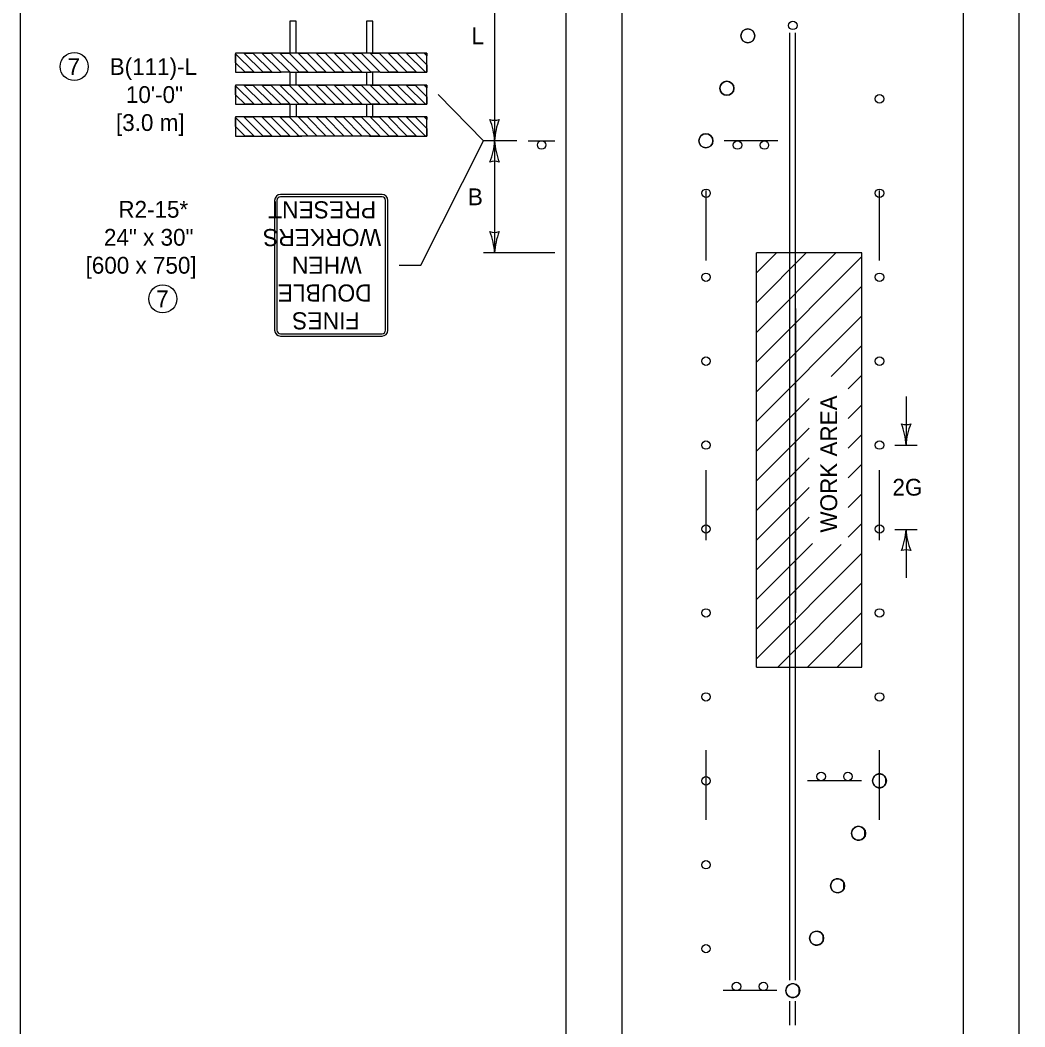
# Model space of a CAD drawing. Extents: x 49991.4 to 50021, y 49987.6 to 50011.4.
# Drawn here: x 50000.336 to 50003.928, y 50003.697 to 50007.296 of the extents above; entities that cross this region are included whole.
import ezdxf

# ---------------------------------------------------------------- set-up
doc = ezdxf.new("R2010")
doc.units = 0
for name, color, linetype in [('Level 1', 7, 'Continuous'), ('Level 2', 7, 'Continuous'), ('Level 3', 7, 'Continuous')]:
    doc.layers.add(name, color=color, linetype=linetype)

msp = doc.modelspace()

# ---------------------------------------------------------------- linework, layer by layer
at = {"layer": 'Level 1'}
for p, q in [((50002.2878, 50001.0309), (50002.2878, 50009.6868)), ((50002.4877, 50001.0309), (50002.4877, 50009.6868)), ((50003.7077, 50001.0309), (50003.7077, 50009.6868)), ((50003.9076, 50001.0309), (50003.9076, 50009.6868)), ((50003.0877, 50003.9389), (50003.0877, 50007.2508)), ((50003.1077, 50004.0147), (50003.1077, 50007.2503)), ((50001.106, 50007.1751), (50001.1719, 50007.1092)), ((50001.106, 50007.1751), (50001.1719, 50007.1092)), ((50001.1357, 50007.1776), (50001.2041, 50007.1092)), ((50001.2041, 50007.1092), (50001.1357, 50007.1776)), ((50001.1679, 50007.1776), (50001.2363, 50007.1092)), ((50001.1679, 50007.1776), (50001.2363, 50007.1092)), ((50001.2002, 50007.1776), (50001.2686, 50007.1092)), ((50001.2686, 50007.1092), (50001.2002, 50007.1776)), ((50001.2324, 50007.1776), (50001.3008, 50007.1092)), ((50001.2324, 50007.1776), (50001.3008, 50007.1092)), ((50001.2646, 50007.1776), (50001.333, 50007.1092)), ((50001.333, 50007.1092), (50001.2646, 50007.1776)), ((50001.2969, 50007.1776), (50001.3653, 50007.1092)), ((50001.2969, 50007.1776), (50001.3653, 50007.1092)), ((50001.3291, 50007.1776), (50001.3975, 50007.1092)), ((50001.3975, 50007.1092), (50001.3291, 50007.1776)), ((50001.3614, 50007.1776), (50001.4297, 50007.1092)), ((50001.3614, 50007.1776), (50001.4297, 50007.1092)), ((50001.3936, 50007.1776), (50001.4619, 50007.1092)), ((50001.4619, 50007.1092), (50001.3936, 50007.1776)), ((50001.4258, 50007.1776), (50001.4942, 50007.1092)), ((50001.4258, 50007.1776), (50001.4942, 50007.1092)), ((50001.4581, 50007.1776), (50001.5265, 50007.1092)), ((50001.5265, 50007.1092), (50001.4581, 50007.1776)), ((50001.4903, 50007.1776), (50001.5587, 50007.1092)), ((50001.4903, 50007.1776), (50001.5587, 50007.1092)), ((50001.5225, 50007.1776), (50001.5909, 50007.1092)), ((50001.5909, 50007.1092), (50001.5225, 50007.1776)), ((50001.5547, 50007.1776), (50001.6231, 50007.1092)), ((50001.5547, 50007.1776), (50001.6231, 50007.1092)), ((50001.587, 50007.1776), (50001.6554, 50007.1092)), ((50001.6554, 50007.1092), (50001.587, 50007.1776)), ((50001.6192, 50007.1776), (50001.6876, 50007.1092)), ((50001.6192, 50007.1776), (50001.6876, 50007.1092)), ((50001.6514, 50007.1776), (50001.7198, 50007.1092)), ((50001.7198, 50007.1092), (50001.6514, 50007.1776)), ((50001.6837, 50007.1776), (50001.7521, 50007.1092)), ((50001.6837, 50007.1776), (50001.7521, 50007.1092)), ((50001.716, 50007.1776), (50001.7844, 50007.1092)), ((50001.7844, 50007.1092), (50001.716, 50007.1776)), ((50001.7482, 50007.1776), (50001.7899, 50007.1359)), ((50001.7482, 50007.1776), (50001.7899, 50007.1359)), ((50001.7804, 50007.1776), (50001.7899, 50007.1681)), ((50001.7899, 50007.1681), (50001.7804, 50007.1776)), ((50001.106, 50007.1429), (50001.1396, 50007.1092)), ((50001.1396, 50007.1092), (50001.106, 50007.1429)), ((50001.106, 50007.0611), (50001.1719, 50006.9953)), ((50001.106, 50007.0611), (50001.1719, 50006.9953)), ((50001.106, 50007.0289), (50001.1396, 50006.9953)), ((50001.1396, 50006.9953), (50001.106, 50007.0289)), ((50001.1357, 50007.0637), (50001.2041, 50006.9953)), ((50001.2041, 50006.9953), (50001.1357, 50007.0637)), ((50001.1679, 50007.0637), (50001.2363, 50006.9953)), ((50001.1679, 50007.0637), (50001.2363, 50006.9953)), ((50001.2002, 50007.0637), (50001.2686, 50006.9953)), ((50001.2686, 50006.9953), (50001.2002, 50007.0637)), ((50001.2324, 50007.0637), (50001.3008, 50006.9953)), ((50001.2324, 50007.0637), (50001.3008, 50006.9953)), ((50001.2646, 50007.0637), (50001.333, 50006.9953)), ((50001.2969, 50007.0637), (50001.3653, 50006.9953)), ((50001.3291, 50007.0637), (50001.3975, 50006.9953)), ((50001.3614, 50007.0637), (50001.4297, 50006.9953)), ((50001.3936, 50007.0637), (50001.4619, 50006.9953)), ((50001.4258, 50007.0637), (50001.4942, 50006.9953)), ((50001.4581, 50007.0637), (50001.5265, 50006.9953)), ((50001.4903, 50007.0637), (50001.5587, 50006.9953)), ((50001.5225, 50007.0637), (50001.5848, 50007.0015)), ((50001.5547, 50007.0637), (50001.5848, 50007.0337)), ((50001.5848, 50007.0337), (50001.6231, 50006.9953)), ((50001.587, 50007.0637), (50001.6554, 50006.9953)), ((50001.6554, 50006.9953), (50001.587, 50007.0637)), ((50001.6192, 50007.0637), (50001.6876, 50006.9953)), ((50001.6192, 50007.0637), (50001.6876, 50006.9953)), ((50001.6514, 50007.0637), (50001.7198, 50006.9953)), ((50001.7198, 50006.9953), (50001.6514, 50007.0637)), ((50001.6837, 50007.0637), (50001.7521, 50006.9953)), ((50001.6837, 50007.0637), (50001.7521, 50006.9953)), ((50001.716, 50007.0637), (50001.7844, 50006.9953)), ((50001.7844, 50006.9953), (50001.716, 50007.0637)), ((50001.7482, 50007.0637), (50001.7899, 50007.022)), ((50001.7482, 50007.0637), (50001.7899, 50007.022)), ((50001.7804, 50007.0637), (50001.7899, 50007.0542)), ((50001.7899, 50007.0542), (50001.7804, 50007.0637)), ((50001.3226, 50006.9953), (50001.3226, 50006.9498)), ((50001.5734, 50006.9953), (50001.5734, 50006.9498)), ((50001.5848, 50007.0015), (50001.5909, 50006.9953)), ((50001.106, 50006.9472), (50001.1719, 50006.8814)), ((50001.106, 50006.9472), (50001.1719, 50006.8814)), ((50001.1357, 50006.9498), (50001.2041, 50006.8814)), ((50001.2041, 50006.8814), (50001.1357, 50006.9498)), ((50001.1679, 50006.9498), (50001.2363, 50006.8814)), ((50001.1679, 50006.9498), (50001.2363, 50006.8814)), ((50001.2002, 50006.9498), (50001.2686, 50006.8814)), ((50001.2686, 50006.8814), (50001.2002, 50006.9498)), ((50001.2324, 50006.9498), (50001.3008, 50006.8814)), ((50001.2324, 50006.9498), (50001.3008, 50006.8814)), ((50001.2646, 50006.9498), (50001.333, 50006.8814)), ((50001.2969, 50006.9498), (50001.3653, 50006.8814)), ((50001.3293, 50006.9498), (50001.3977, 50006.8814)), ((50001.3615, 50006.9498), (50001.4299, 50006.8814)), ((50001.3937, 50006.9498), (50001.4621, 50006.8814)), ((50001.4259, 50006.9498), (50001.4943, 50006.8814)), ((50001.4581, 50006.9498), (50001.5265, 50006.8814)), ((50001.4903, 50006.9498), (50001.5587, 50006.8814)), ((50001.5225, 50006.9498), (50001.5909, 50006.8814)), ((50001.5547, 50006.9498), (50001.6231, 50006.8814)), ((50001.587, 50006.9498), (50001.6554, 50006.8814)), ((50001.6554, 50006.8814), (50001.587, 50006.9498)), ((50001.6192, 50006.9498), (50001.6876, 50006.8814)), ((50001.6192, 50006.9498), (50001.6876, 50006.8814)), ((50001.6514, 50006.9498), (50001.7198, 50006.8814)), ((50001.7198, 50006.8814), (50001.6514, 50006.9498)), ((50001.6837, 50006.9498), (50001.7521, 50006.8814)), ((50001.6837, 50006.9498), (50001.7521, 50006.8814)), ((50001.716, 50006.9498), (50001.7844, 50006.8814)), ((50001.7844, 50006.8814), (50001.716, 50006.9498)), ((50001.7482, 50006.9498), (50001.7899, 50006.908)), ((50001.7482, 50006.9498), (50001.7899, 50006.908)), ((50001.7804, 50006.9498), (50001.7899, 50006.9403)), ((50001.7899, 50006.9403), (50001.7804, 50006.9498)), ((50001.106, 50006.915), (50001.1396, 50006.8814)), ((50001.1396, 50006.8814), (50001.106, 50006.915)), ((50001.3112, 50006.8814), (50001.3425, 50006.8814)), ((50001.5705, 50006.8814), (50001.3254, 50006.8814)), ((50001.5909, 50006.8814), (50001.551, 50006.8814)), ((50002.1518, 50006.8644), (50002.2478, 50006.8644)), ((50002.9483, 50006.8644), (50002.8523, 50006.8644)), ((50003.0443, 50006.8644), (50002.9483, 50006.8644)), ((50001.6294, 50006.6726), (50001.2665, 50006.6726)), ((50002.7879, 50006.4368), (50002.7879, 50006.6868)), ((50003.4079, 50006.4368), (50003.4079, 50006.6868)), ((50001.2454, 50006.6515), (50001.2454, 50006.1874)), ((50001.2539, 50006.6515), (50001.2539, 50006.1874)), ((50001.6294, 50006.6642), (50001.2665, 50006.6642)), ((50001.6421, 50006.1874), (50001.6421, 50006.6515)), ((50001.6505, 50006.1874), (50001.6505, 50006.6515)), ((50003.3453, 50006.4637), (50002.9682, 50006.4637)), ((50002.9682, 50004.9833), (50002.9682, 50006.4637)), ((50002.9682, 50006.2856), (50003.1463, 50006.4637)), ((50002.9682, 50006.1795), (50003.2524, 50006.4637)), ((50002.9682, 50006.3918), (50003.0401, 50006.4637)), ((50003.3453, 50004.9833), (50003.3453, 50006.4637)), ((50002.9682, 50006.0735), (50003.3453, 50006.4506)), ((50002.9682, 50005.9674), (50003.3453, 50006.3445)), ((50002.9682, 50005.8613), (50003.3453, 50006.2384)), ((50003.1077, 50006.2644), (50003.1077, 50005.1767)), ((50001.2665, 50006.1747), (50001.6294, 50006.1747)), ((50001.2665, 50006.1663), (50001.6294, 50006.1663)), ((50003.2349, 50006.0219), (50003.3453, 50006.1324)), ((50003.2965, 50005.9775), (50003.3453, 50006.0263)), ((50002.9682, 50005.7553), (50003.1565, 50005.9436)), ((50003.2965, 50005.8714), (50003.3453, 50005.9202)), ((50003.2965, 50005.8714), (50003.2965, 50005.8714)), ((50002.9682, 50005.6492), (50003.1565, 50005.8375)), ((50003.2965, 50005.7654), (50003.3453, 50005.8142)), ((50003.2965, 50005.7654), (50003.2965, 50005.7654)), ((50002.9682, 50005.5432), (50003.1565, 50005.7314)), ((50003.2965, 50005.6593), (50003.3453, 50005.7081)), ((50002.7879, 50005.4368), (50002.7879, 50005.6868)), ((50003.4079, 50005.4368), (50003.4079, 50005.6868)), ((50002.9682, 50005.4371), (50003.1565, 50005.6254)), ((50003.2965, 50005.6593), (50003.2965, 50005.6593)), ((50003.2965, 50005.5532), (50003.3453, 50005.602)), ((50002.9682, 50005.331), (50003.1565, 50005.5193)), ((50003.2965, 50005.4472), (50003.3453, 50005.496)), ((50002.9682, 50005.1189), (50003.2705, 50005.4211)), ((50002.9682, 50005.225), (50003.1565, 50005.4132)), ((50003.1565, 50005.4132), (50003.1684, 50005.4251)), ((50002.9682, 50005.0128), (50003.3453, 50005.3899)), ((50003.0448, 50004.9833), (50003.3453, 50005.2838)), ((50003.1509, 50004.9833), (50003.3453, 50005.1778)), ((50003.2569, 50004.9833), (50003.3453, 50005.0717)), ((50002.9682, 50004.9833), (50003.3453, 50004.9833)), ((50002.7879, 50004.4368), (50002.7879, 50004.6868)), ((50003.4079, 50004.4368), (50003.4079, 50004.6868)), ((50003.2471, 50004.5767), (50003.1511, 50004.5767)), ((50003.3431, 50004.5767), (50003.2471, 50004.5767)), ((50003.1077, 50003.8647), (50003.1077, 50004.0147)), ((50003.0877, 50003.8647), (50003.0877, 50003.9389)), ((50002.9448, 50003.8267), (50002.8488, 50003.8267)), ((50003.0408, 50003.8267), (50002.9448, 50003.8267)), ((50003.0877, 50003.7029), (50003.0877, 50003.7887)), ((50003.1077, 50003.7029), (50003.1077, 50003.7887))]:
    msp.add_line(p, q, dxfattribs=at)
msp.add_lwpolyline([(50008.6146, 50011.2628), (50000.3356, 50011.2628), (50000.3356, 50000.0624), (50008.6146, 50000.0624)], close=True, dxfattribs=at)
for points in [[(50001.3226, 50007.1778), (50001.3226, 50007.2917), (50001.2998, 50007.2917), (50001.2998, 50007.1778)], [(50001.5962, 50007.1778), (50001.5962, 50007.2917), (50001.5734, 50007.2917), (50001.5734, 50007.1778)], [(50001.6231, 50007.1092), (50001.7899, 50007.1092), (50001.7899, 50007.1776), (50001.106, 50007.1776), (50001.106, 50007.1092), (50001.2686, 50007.1092)], [(50001.106, 50007.1429), (50001.106, 50007.1751)], [(50001.1357, 50007.1776), (50001.1679, 50007.1776)], [(50001.2002, 50007.1776), (50001.2324, 50007.1776)], [(50001.2646, 50007.1776), (50001.2969, 50007.1776)], [(50001.3291, 50007.1776), (50001.3614, 50007.1776)], [(50001.3936, 50007.1776), (50001.4258, 50007.1776)], [(50001.4581, 50007.1776), (50001.4903, 50007.1776)], [(50001.5225, 50007.1776), (50001.5547, 50007.1776)], [(50001.587, 50007.1776), (50001.6192, 50007.1776)], [(50001.6514, 50007.1776), (50001.6837, 50007.1776)], [(50001.716, 50007.1776), (50001.7482, 50007.1776)], [(50001.7804, 50007.1776), (50001.7899, 50007.1776), (50001.7899, 50007.1681)], [(50001.1719, 50007.1092), (50001.1396, 50007.1092)], [(50001.2363, 50007.1092), (50001.2041, 50007.1092)], [(50001.3008, 50007.1092), (50001.2686, 50007.1092)], [(50001.2998, 50007.1092), (50001.2998, 50007.0637)], [(50001.3008, 50007.1092), (50001.5909, 50007.1092)], [(50001.3226, 50007.0637), (50001.3226, 50007.1092)], [(50001.3653, 50007.1092), (50001.333, 50007.1092)], [(50001.4297, 50007.1092), (50001.3975, 50007.1092)], [(50001.4942, 50007.1092), (50001.4619, 50007.1092)], [(50001.5587, 50007.1092), (50001.5265, 50007.1092)], [(50001.5734, 50007.1092), (50001.5734, 50007.0637)], [(50001.6231, 50007.1092), (50001.5909, 50007.1092)], [(50001.5962, 50007.0637), (50001.5962, 50007.1092)], [(50001.6876, 50007.1092), (50001.6554, 50007.1092)], [(50001.7521, 50007.1092), (50001.7198, 50007.1092)], [(50001.7899, 50007.1359), (50001.7899, 50007.1092), (50001.7844, 50007.1092)], [(50001.5848, 50006.9953), (50001.7899, 50006.9953), (50001.7899, 50007.0637), (50001.106, 50007.0637), (50001.106, 50006.9953), (50001.5848, 50006.9953)], [(50001.106, 50007.0289), (50001.106, 50007.0611)], [(50001.1357, 50007.0637), (50001.1679, 50007.0637)], [(50001.2002, 50007.0637), (50001.2324, 50007.0637)], [(50001.3653, 50006.9953), (50001.333, 50006.9953), (50001.2646, 50007.0637), (50001.2969, 50007.0637), (50001.3653, 50006.9953)], [(50001.4297, 50006.9953), (50001.3975, 50006.9953), (50001.3291, 50007.0637), (50001.3614, 50007.0637), (50001.4297, 50006.9953)], [(50001.4942, 50006.9953), (50001.4619, 50006.9953), (50001.3936, 50007.0637), (50001.4258, 50007.0637), (50001.4942, 50006.9953)], [(50001.5587, 50006.9953), (50001.5265, 50006.9953), (50001.4581, 50007.0637), (50001.4903, 50007.0637), (50001.5587, 50006.9953)], [(50001.5225, 50007.0637), (50001.5547, 50007.0637), (50001.5848, 50007.0337), (50001.6231, 50006.9953), (50001.5962, 50006.9953), (50001.5909, 50006.9953), (50001.5848, 50007.0015), (50001.5225, 50007.0637)], [(50001.587, 50007.0637), (50001.6192, 50007.0637)], [(50001.6514, 50007.0637), (50001.6837, 50007.0637)], [(50001.716, 50007.0637), (50001.7482, 50007.0637)], [(50001.7804, 50007.0637), (50001.7899, 50007.0637), (50001.7899, 50007.0542)], [(50001.1719, 50006.9953), (50001.1396, 50006.9953)], [(50001.2363, 50006.9953), (50001.2041, 50006.9953)], [(50001.3008, 50006.9953), (50001.2686, 50006.9953)], [(50001.2998, 50006.9954), (50001.2998, 50006.9498)], [(50001.5962, 50006.9498), (50001.5962, 50006.9953)], [(50001.6876, 50006.9953), (50001.6554, 50006.9953)], [(50001.7521, 50006.9953), (50001.7198, 50006.9953)], [(50001.7899, 50007.022), (50001.7899, 50006.9953), (50001.7844, 50006.9953)], [(50001.5848, 50006.9498), (50001.106, 50006.9498), (50001.106, 50006.8814), (50001.3112, 50006.8814)], [(50001.106, 50006.915), (50001.106, 50006.9472)], [(50001.1357, 50006.9498), (50001.1679, 50006.9498)], [(50001.2002, 50006.9498), (50001.2324, 50006.9498)], [(50001.3653, 50006.8814), (50001.3425, 50006.8814), (50001.333, 50006.8814), (50001.2646, 50006.9498), (50001.2969, 50006.9498), (50001.3653, 50006.8814)], [(50001.4299, 50006.8814), (50001.3977, 50006.8814), (50001.3293, 50006.9498), (50001.3615, 50006.9498), (50001.4299, 50006.8814)], [(50001.4943, 50006.8814), (50001.4621, 50006.8814), (50001.3937, 50006.9498), (50001.4259, 50006.9498), (50001.4943, 50006.8814)], [(50001.5587, 50006.8814), (50001.551, 50006.8814), (50001.5265, 50006.8814), (50001.4581, 50006.9498), (50001.4903, 50006.9498), (50001.5587, 50006.8814)], [(50001.5225, 50006.9498), (50001.5547, 50006.9498), (50001.6231, 50006.8814), (50001.5909, 50006.8814), (50001.5225, 50006.9498)], [(50001.5848, 50006.8814), (50001.7899, 50006.8814), (50001.7899, 50006.9498), (50001.5848, 50006.9498)], [(50001.587, 50006.9498), (50001.6192, 50006.9498)], [(50001.6514, 50006.9498), (50001.6837, 50006.9498)], [(50001.716, 50006.9498), (50001.7482, 50006.9498)], [(50001.7804, 50006.9498), (50001.7899, 50006.9498), (50001.7899, 50006.9403)], [(50001.7899, 50006.908), (50001.7899, 50006.8814), (50001.7844, 50006.8814)], [(50001.1719, 50006.8814), (50001.1396, 50006.8814)], [(50001.2363, 50006.8814), (50001.2041, 50006.8814)], [(50001.3008, 50006.8814), (50001.2686, 50006.8814)], [(50001.6876, 50006.8814), (50001.6554, 50006.8814)], [(50001.7521, 50006.8814), (50001.7198, 50006.8814)], [(50003.4311, 50004.5668), (50003.4311, 50004.5866)], [(50003.4311, 50004.5866), (50003.4311, 50004.5668)], [(50003.356, 50004.3793), (50003.356, 50004.3991)], [(50003.356, 50004.3991), (50003.356, 50004.3793)], [(50003.281, 50004.1918), (50003.281, 50004.2116)], [(50003.281, 50004.2116), (50003.281, 50004.1918)], [(50003.206, 50004.0043), (50003.206, 50004.0241)], [(50003.206, 50004.0241), (50003.206, 50004.0043)], [(50003.1209, 50003.8168), (50003.1209, 50003.8366)], [(50003.1209, 50003.8366), (50003.1209, 50003.8168)]]:
    msp.add_lwpolyline(points, dxfattribs=at)
for centre, radius in [((50003.098, 50007.2767), 0.015), ((50002.9374, 50007.2394), 0.025), ((50002.8624, 50007.0519), 0.025), ((50003.4079, 50007.0144), 0.015), ((50002.7873, 50006.8644), 0.025), ((50002.1999, 50006.8493), 0.0152), ((50002.9003, 50006.8492), 0.0152), ((50002.9963, 50006.8492), 0.0152), ((50002.7879, 50006.6767), 0.015), ((50003.4079, 50006.6767), 0.015), ((50002.7876, 50006.3767), 0.015), ((50003.4079, 50006.3767), 0.015), ((50002.7876, 50006.0767), 0.015), ((50003.4079, 50006.0767), 0.015), ((50002.7876, 50005.7767), 0.015), ((50003.4079, 50005.7767), 0.015), ((50002.7876, 50005.4767), 0.015), ((50003.4079, 50005.4767), 0.015), ((50002.7876, 50005.1767), 0.015), ((50003.4079, 50005.1767), 0.015), ((50002.7876, 50004.8767), 0.015), ((50003.4079, 50004.8767), 0.015), ((50002.7876, 50004.5767), 0.015), ((50003.1991, 50004.5919), 0.0152), ((50003.2951, 50004.5919), 0.0152), ((50003.4081, 50004.5767), 0.025), ((50003.3331, 50004.3892), 0.025), ((50002.7876, 50004.2767), 0.015), ((50003.2581, 50004.2017), 0.025), ((50003.183, 50004.0142), 0.025), ((50002.7876, 50003.9767), 0.015), ((50002.8968, 50003.8419), 0.0152), ((50002.9928, 50003.8419), 0.0152), ((50003.098, 50003.8267), 0.025)]:
    msp.add_circle(centre, radius, dxfattribs=at)
for centre, radius, start, end in [((50002.9374, 50007.2394), 0.025, 0, 180), ((50002.9374, 50007.2394), 0.025, 180, 0), ((50002.8624, 50007.0519), 0.025, 0, 180), ((50002.8624, 50007.0519), 0.025, 180, 0), ((50002.7873, 50006.8644), 0.025, 0, 180), ((50002.7873, 50006.8644), 0.025, 180, 0), ((50001.2665, 50006.6515), 0.0211, 90, 180), ((50001.6293, 50006.6515), 0.0211, 360, 90), ((50001.2665, 50006.6515), 0.0127, 90, 180), ((50001.6293, 50006.6515), 0.0127, 360, 90), ((50001.2665, 50006.1874), 0.0211, 180, 270), ((50001.2665, 50006.1874), 0.0127, 180, 270), ((50001.6293, 50006.1874), 0.0211, 270, 360), ((50001.6293, 50006.1874), 0.0127, 270, 360), ((50003.4081, 50004.5767), 0.025, 23.4057, 180), ((50003.4081, 50004.5767), 0.025, 360, 23.4057), ((50003.4081, 50004.5767), 0.025, 180, 336.5943), ((50003.4081, 50004.5767), 0.025, 336.5943, 0), ((50003.3331, 50004.3892), 0.025, 23.4057, 180), ((50003.3331, 50004.3892), 0.025, 180, 336.5943), ((50003.3331, 50004.3892), 0.025, 360, 23.4057), ((50003.3331, 50004.3892), 0.025, 336.5943, 0), ((50003.2581, 50004.2017), 0.025, 23.4057, 180), ((50003.2581, 50004.2017), 0.025, 180, 336.5943), ((50003.2581, 50004.2017), 0.025, 360, 23.4057), ((50003.2581, 50004.2017), 0.025, 336.5943, 0), ((50003.183, 50004.0142), 0.025, 23.4057, 180), ((50003.183, 50004.0142), 0.025, 180, 336.5943), ((50003.183, 50004.0142), 0.025, 360, 23.4057), ((50003.183, 50004.0142), 0.025, 336.5943, 0), ((50003.098, 50003.8267), 0.025, 23.4057, 180), ((50003.098, 50003.8267), 0.025, 180, 336.5943), ((50003.098, 50003.8267), 0.025, 360, 23.4057), ((50003.098, 50003.8267), 0.025, 336.5943, 0)]:
    msp.add_arc(centre, radius, start, end, dxfattribs=at)
at = {"layer": 'Level 2'}
for centre in [(50000.5289, 50007.1296), (50000.8457, 50006.2994)]:
    msp.add_circle(centre, 0.0501, dxfattribs=at)
at = {"layer": 'Level 3'}
for p, q in [((50002.0318, 50007.6144), (50002.0318, 50006.8644)), ((50001.9918, 50006.8644), (50001.8299, 50007.0295)), ((50001.768, 50006.4194), (50001.9918, 50006.8644)), ((50002.1118, 50006.8644), (50001.9918, 50006.8644)), ((50002.0318, 50006.8644), (50002.0318, 50006.4637)), ((50002.2478, 50006.4637), (50001.9918, 50006.4637)), ((50001.6905, 50006.4194), (50001.768, 50006.4194)), ((50003.5029, 50005.9501), (50003.5029, 50005.7767)), ((50003.4629, 50005.7767), (50003.5429, 50005.7767)), ((50003.4629, 50005.4755), (50003.5429, 50005.4755)), ((50003.5029, 50005.4755), (50003.5029, 50005.3021))]:
    msp.add_line(p, q, dxfattribs=at)
for centre, radius, start, end in [((50002.0318, 50006.9927), 0.0548, 252.1388, 287.8612), ((50001.7991, 50006.853), 0.233, 2.8273, 22.0772), ((50002.254, 50006.8553), 0.2223, 157.456, 177.6395), ((50001.8097, 50006.8736), 0.2223, 337.456, 357.6395), ((50002.2645, 50006.8759), 0.233, 182.8273, 202.0772), ((50002.0318, 50006.7362), 0.0548, 72.1388, 107.8612), ((50002.0318, 50006.5919), 0.0548, 252.1388, 287.8612), ((50001.7991, 50006.4522), 0.233, 2.8273, 22.0772), ((50002.254, 50006.4545), 0.2223, 157.456, 177.6395), ((50003.5029, 50005.9049), 0.0548, 252.1388, 287.8612), ((50003.2702, 50005.7652), 0.233, 2.8273, 22.0772), ((50003.725, 50005.7675), 0.2223, 157.456, 177.6395), ((50003.2807, 50005.4846), 0.2223, 337.456, 357.6395), ((50003.7356, 50005.487), 0.233, 182.8273, 202.0772), ((50003.5029, 50005.3473), 0.0548, 72.1388, 107.8612)]:
    msp.add_arc(centre, radius, start, end, dxfattribs=at)

# ---------------------------------------------------------------- texts
at = {"layer": 'Level 1'}
for s, p in [('PRESENT', (50001.6083, 50006.6483)), ('WORKERS', (50001.6264, 50006.5491)), ('WHEN', (50001.557, 50006.45)), ('DOUBLE', (50001.5925, 50006.3508)), ('FINES', (50001.549, 50006.2516))]:
    msp.add_text(s, height=0.06118, rotation=180, dxfattribs=at).set_placement(p)
at = {"layer": 'Level 2'}
for s, rotation, p in [('L', 360, (50001.9494, 50007.2094)), ('B', 360, (50001.9363, 50006.6341)), ('WORK AREA', 90, (50003.2565, 50005.4639)), ('2G', 360, (50003.4542, 50005.5961))]:
    msp.add_text(s, height=0.06, rotation=rotation, dxfattribs=at).set_placement(p)
for s, p in [('7', (50000.5051, 50007.0996)), ('B(111)-L', (50000.6558, 50007.0995)), ('10\'-0"', (50000.7136, 50006.9995)), ('[3.0 m]', (50000.6783, 50006.8995)), ('R2-15*', (50000.6867, 50006.5894)), ('24" x 30"', (50000.6352, 50006.4894)), ('[600 x 750]', (50000.5696, 50006.3894)), ('7', (50000.8219, 50006.2694))]:
    msp.add_text(s, height=0.06, dxfattribs=at).set_placement(p)

doc.saveas('drawing.dxf')
